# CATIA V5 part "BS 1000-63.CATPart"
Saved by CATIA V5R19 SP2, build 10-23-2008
Part number: BS 1000-63
Bounding box of the stored display mesh (mm): x -24.865 to 24.865, y -24.997 to 24.997, z 0 to 164
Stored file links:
  C:\Users\Bora\Desktop\3D Katı model\BS serisi\BS 1000\BS 1000-63.CATPart
  C:\Program Files\Dassault Systemes\B19\intel_a\reffiles\standard\MetricThickPitch.txt
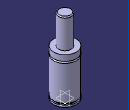
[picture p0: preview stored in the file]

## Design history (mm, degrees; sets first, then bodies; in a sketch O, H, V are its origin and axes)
Body1 (main body)
  Sketch1 on yz-plane, origin (0, 0, 0), H (0, 1, 0), V (0, 0, 1)
    point P2 (14, 162)
    line L1 (14, 162) -> (14, 100)
    point P3 (25, 87.5)
    line L2 (25, 100) -> (25, 87.5)
    point P6 (25, 83.5)
    line L3 (25, 83.5) -> (25, 7.5)
    line L4 (25, 4) -> (25, 0)
    point P9 (25, 83.5)
    point P10 (25, 87.5)
    arc A1 centre (25, 85.5) radius 2 from (25, 87.5) to (25, 83.5) ccw
    point P12 (14, 162)
    arc A2 centre (12, 162) radius 2 from (14, 162) to (12, 164) ccw
    line L5 (22.5, 7.5) -> (22.5, 4)
    line L6 (12, 164) -> (0, 164)
    point P15 (0, 164)
    line L7 (14, 100) -> (25, 100)
    line L8 (0, 0) -> (25, 0)
    line L9 (22.5, 7.5) -> (25, 7.5)
    line L10 (22.5, 4) -> (25, 4)
    coincidence: P15 V, P2 P12, P3 P10, P6 P9
    tangency: L6 A2
    horizontal: L7 H, L8 H, L9 H, L10 H
  Shaft1: profile Sketch1, axis Sketch1.V, angle 360
  Sketch2 on face of Shaft1 from Sketch1.L8, origin (0, 0, 0), H (1, 0, 0), V (0, -1, 0)
    point P1 (10, 0)
    distance P1 V = 10
  Hole1: placed by Sketch2, at (10, 0, 0) direction (0, 0, 1), diameter 6.647, depth 6, threaded "M8", thread diameter 8, thread depth 6, pitch 1.25
  CircPattern1: of Hole1, instances 2, angular step 180, axis from xy-plane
